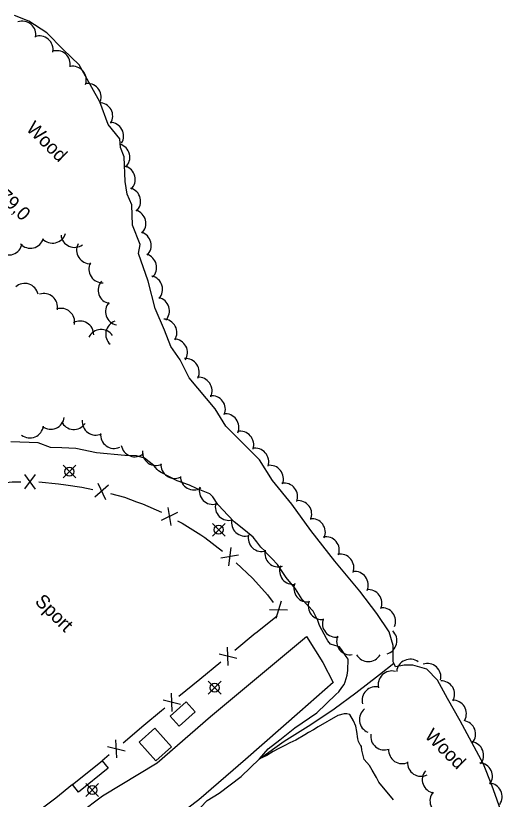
# Model space of a CAD drawing. Extents: x 642515 to 647219, y 6080136 to 6084356.
# Drawn here: x 643817.9 to 643926.8, y 6082164.2 to 6082337 of the extents above; entities that cross this region are included whole.
import ezdxf

# ---------------------------------------------------------------- set-up
doc = ezdxf.new("R2010")
doc.units = 0
for name, color, linetype in [('Level 1', 7, 'Continuous'), ('Level 19', 7, 'Continuous'), ('Level 3', 7, 'Continuous'), ('Level 31', 7, 'Continuous'), ('Level 36', 7, 'Continuous'), ('Level 37', 7, 'Continuous'), ('Level 4', 7, 'Continuous'), ('Level 44', 7, 'Continuous'), ('Level 56', 7, 'Continuous')]:
    doc.layers.add(name, color=color, linetype=linetype)

msp = doc.modelspace()

# ---------------------------------------------------------------- linework, layer by layer
at = {"layer": 'Level 1'}
for points in [[(643875.66, 6082215.94), (643874.38, 6082217.32), (643873.78, 6082217.85), (643873.18, 6082218.55), (643872.92, 6082218.93), (643871.95, 6082219.81), (643871.12, 6082220.93), (643870.3, 6082221.97), (643868.61, 6082223.42), (643866.09, 6082225.37), (643863.53, 6082228.06), (643862.76, 6082228.9), (643862.46, 6082229.17), (643861.41, 6082230.88), (643860.69, 6082231.53), (643857.76, 6082232.7), (643856.26, 6082233.43), (643853.5, 6082234.45), (643849.97, 6082236.24), (643849.38, 6082236.61), (643849.12, 6082236.92), (643848.39, 6082237.81), (643846.29, 6082239.39), (643844.52, 6082239.9), (643842.01, 6082240.01), (643835.7, 6082240.6), (643831.19, 6082241.57), (643828.07, 6082241.69), (643825.59, 6082241.76), (643822.83, 6082242.79), (643816.82, 6082243.03)], [(643894.75, 6082172.96), (643894.21, 6082174.98), (643894.17, 6082175.78), (643894.04, 6082176.05), (643893.91, 6082176.17), (643893.51, 6082176.91), (643893.36, 6082177.5), (643893.16, 6082179.14), (643892.94, 6082180.33), (643892.4, 6082181.51), (643891.56, 6082182.87), (643890.91, 6082183), (643890.34, 6082183.05), (643888.98, 6082182.66), (643884.61, 6082180.14), (643883.55, 6082179.48), (643882.49, 6082178.9), (643881.7, 6082178.38), (643879.7, 6082177.19), (643878.39, 6082176.6), (643877.28, 6082176.06), (643875.94, 6082175.34), (643874.72, 6082174.68), (643873.3, 6082173.8), (643871.64, 6082173.07), (643873.55, 6082175.29), (643876.13, 6082177.27), (643879.44, 6082179.9), (643884.34, 6082183.25), (643888.52, 6082187.25), (643889.16, 6082187.86), (643889.86, 6082188.8), (643890.33, 6082189.49), (643890.57, 6082190.05), (643891.02, 6082191.52), (643891.12, 6082192.55), (643891.2, 6082195.08), (643890.76, 6082195.7), (643890.33, 6082196.32), (643889.89, 6082197.02), (643889.28, 6082197.8), (643888.26, 6082198.1), (643887.31, 6082198.42), (643886.71, 6082199.11), (643886.48, 6082199.62), (643884.89, 6082202.51), (643884.51, 6082203.62), (643883.48, 6082205.69), (643881.05, 6082208.26), (643879.6, 6082210.56), (643877.58, 6082213.06), (643875.66, 6082215.94)], [(643901.25, 6082164.06), (643897.98, 6082167.98), (643897.45, 6082169), (643896.52, 6082170.6), (643895.91, 6082171.61), (643894.75, 6082172.96)]]:
    msp.add_lwpolyline(points, dxfattribs=at)
at = {"layer": 'Level 19'}
msp.add_lwpolyline([(643831.96, 6082161.14), (643837.04, 6082164.9), (643849.08, 6082172.18), (643860.87, 6082182.46), (643882.02, 6082200.06), (643885.62, 6082194.35), (643887.93, 6082189.96), (643880.56, 6082183.47), (643868.57, 6082172.98), (643858.29, 6082164.03), (643848.88, 6082156.93), (643843.91, 6082153.54), (643841.75, 6082152.29)], dxfattribs=at)
at = {"layer": 'Level 31'}
msp.add_lwpolyline([(643838.27, 6082171), (643831.76, 6082165.77), (643830.44, 6082167.41), (643836.99, 6082172.66), (643838.27, 6082171)], dxfattribs=at)
at = {"layer": 'Level 36'}
for p, q in [((643831.17, 6082235.05), (643828.35, 6082237.87)), ((643828.35, 6082235.05), (643831.17, 6082237.87)), ((643864.1, 6082222.22), (643861.28, 6082225.04)), ((643861.28, 6082222.22), (643864.1, 6082225.04)), ((643863.21, 6082187.38), (643860.39, 6082190.2)), ((643860.39, 6082187.38), (643863.21, 6082190.2)), ((643836.2, 6082164.8), (643833.38, 6082167.62)), ((643833.38, 6082164.8), (643836.2, 6082167.62))]:
    msp.add_line(p, q, dxfattribs=at)
for centre in [(643829.76, 6082236.46), (643862.69, 6082223.63), (643861.8, 6082188.79), (643834.79, 6082166.21)]:
    msp.add_circle(centre, 1, dxfattribs=at)
at = {"layer": 'Level 37'}
for p, q in [((643822.24, 6082235.81), (643819.83, 6082232.62)), ((643819.84, 6082235.82), (643822.23, 6082232.61)), ((643836.01, 6082233.93), (643837.74, 6082230.33)), ((643838.36, 6082233.47), (643835.39, 6082230.79)), ((643851.49, 6082228.53), (643852.14, 6082224.58)), ((643853.62, 6082227.42), (643850.02, 6082225.69)), ((643865.32, 6082219.68), (643864.87, 6082215.7)), ((643867.07, 6082218.03), (643863.12, 6082217.35)), ((643876.46, 6082207.85), (643875.31, 6082204.02)), ((643875.57, 6082204.53), (643870.85, 6082200.83)), ((643877.88, 6082205.92), (643873.89, 6082205.96)), ((643864.8, 6082193.72), (643864.6, 6082197.72)), ((643866.64, 6082195.26), (643862.75, 6082196.18)), ((643863.16, 6082194.44), (643858.52, 6082190.63)), ((643858.52, 6082190.63), (643853.89, 6082186.82)), ((643852.43, 6082183.56), (643852.25, 6082187.56)), ((643854.28, 6082185.08), (643850.4, 6082186.03)), ((643846.2, 6082180.42), (643841.61, 6082176.56)), ((643840.2, 6082173.28), (643839.97, 6082177.27)), ((643842.03, 6082174.82), (643838.14, 6082175.72)), ((643838.55, 6082173.98), (643836.99, 6082172.66)), ((643830.44, 6082167.41), (643826.77, 6082164.44))]:
    msp.add_line(p, q, dxfattribs=at)
for points in [[(643813.07, 6082233.79), (643817.14, 6082234.23), (643819.04, 6082234.22)], [(643823.04, 6082234.2), (643827.36, 6082233.75), (643829, 6082233.51)], [(643829, 6082233.51), (643832.48, 6082233), (643834.92, 6082232.52)], [(643838.82, 6082231.64), (643841.94, 6082230.81), (643844.52, 6082229.82)], [(643844.52, 6082229.82), (643845.84, 6082229.31), (643850.05, 6082227.47)], [(643853.6, 6082225.63), (643854.64, 6082225.09), (643858.71, 6082222.49)], [(643858.71, 6082222.49), (643859.64, 6082221.9), (643863.52, 6082218.91)], [(643866.55, 6082216.32), (643870.12, 6082212.95), (643870.85, 6082212.14)], [(643870.85, 6082212.14), (643873.45, 6082209.26), (643874.71, 6082207.55)], [(643870.85, 6082200.83), (643870.7, 6082200.72), (643866.23, 6082197)], [(643850.8, 6082184.28), (643850.04, 6082183.66), (643846.2, 6082180.42)], [(643826.77, 6082164.44), (643822.38, 6082161.1), (643821.9, 6082161.12)]]:
    msp.add_lwpolyline(points, dxfattribs=at)
at = {"layer": 'Level 4'}
for points in [[(643852.13, 6082264.04), (643850.71, 6082267.64), (643848.65, 6082272.42), (643847.1, 6082278.46), (643844.97, 6082284.55), (643845.36, 6082286.52), (643843.65, 6082290.84), (643843.49, 6082295.32), (643842.47, 6082297.63), (643842.07, 6082300.46), (643841.85, 6082305.92), (643841.01, 6082307.92), (643840.9, 6082309.87), (643838.28, 6082313), (643836.46, 6082318.04), (643831.9, 6082326.17), (643828.41, 6082329.54), (643824.78, 6082333.27), (643820.8, 6082335.84), (643817.68, 6082337.03)], [(643926.77, 6082156.3), (643922.91, 6082167.32), (643921.04, 6082171.95), (643915.96, 6082181.45), (643913.17, 6082186.43), (643910.91, 6082190.47), (643908.59, 6082192.87), (643905.52, 6082193.77), (643903.61, 6082193.79), (643901.63, 6082193.41), (643901.3, 6082194.2), (643901.17, 6082194.52), (643901.18, 6082198.07), (643900.28, 6082201.11), (643897.58, 6082205.17), (643893.81, 6082210.1), (643888.27, 6082216.7), (643883.02, 6082223.43), (643878.79, 6082229.24), (643874.52, 6082234.48), (643871.66, 6082239.05), (643868.99, 6082241.77), (643864.25, 6082246.49), (643861.92, 6082250.28), (643856.17, 6082257.16), (643854.16, 6082261.13), (643852.13, 6082264.04)], [(643845.87, 6082148.45), (643849.78, 6082152.72), (643854.12, 6082157.37), (643857.19, 6082160.78), (643860.15, 6082163.9), (643862.78, 6082165.54), (643867.62, 6082169.2), (643871.64, 6082173.07), (643877.12, 6082177.01), (643883.02, 6082180.65), (643888.12, 6082184.09), (643892.89, 6082187.67), (643898.13, 6082191.69), (643901.3, 6082194.2)]]:
    msp.add_lwpolyline(points, dxfattribs=at)
at = {"layer": 'Level 44'}
for centre, start, end in [((643819.35, 6082332.82), 349.4544, 109.4324), ((643823.15, 6082329.56), 349.4544, 109.4324), ((643826.95, 6082326.31), 349.4544, 109.4324), ((643830.48, 6082322.86), 340.9078, 100.8858), ((643833.76, 6082319.08), 340.9078, 100.8858), ((643836.31, 6082314.87), 328.7495, 88.7274), ((643838.71, 6082310.49), 328.7495, 88.7274), ((643840.08, 6082305.78), 313.9631, 73.941), ((643841.28, 6082300.93), 313.9631, 73.941), ((643842.46, 6082296.07), 313.5451, 73.523), ((643843.63, 6082291.21), 313.5451, 73.523), ((643826.03, 6082289.86), 223.1117, 343.0897), ((643844.8, 6082286.35), 313.781, 73.7589), ((643821.16, 6082288.73), 223.1117, 343.0897), ((643830.89, 6082288.92), 185.8795, 305.8574), ((643816.36, 6082287.24), 229.5062, 349.4841), ((643834.33, 6082285.31), 152.7566, 272.7345), ((643845.99, 6082281.49), 313.781, 73.7589), ((643837.04, 6082281.1), 152.7566, 272.7345), ((643847.31, 6082276.65), 317.5724, 77.5504), ((643819.91, 6082274.97), 11.8032, 131.7812), ((643839.08, 6082276.49), 138.9354, 258.9133), ((643824.15, 6082272.75), 348.8748, 108.8528), ((643840.7, 6082271.76), 138.9354, 258.9133), ((643848.82, 6082271.88), 317.5724, 77.5504), ((643827.91, 6082269.46), 348.8748, 108.8528), ((643850.46, 6082267.11), 327.915, 87.893), ((643832.11, 6082266.67), 358.6278, 118.6057), ((643840.75, 6082266.78), 108.4417, 228.4197), ((643836.74, 6082264.79), 33.4091, 153.387), ((643852.8, 6082262.7), 327.915, 87.893), ((643855.39, 6082258.39), 334.4749, 94.4528), ((643858.22, 6082254.27), 334.4749, 94.4528), ((643861.14, 6082250.19), 337.0956, 97.0736), ((643825.66, 6082248.8), 232.4915, 352.4694), ((643835.58, 6082247.5), 174.0407, 294.0186), ((643864.15, 6082246.2), 337.0956, 97.0736), ((643821.04, 6082246.89), 232.4915, 352.4694), ((643830.74, 6082248.75), 205.56, 325.5379), ((643839.62, 6082244.57), 174.0407, 294.0186), ((643867.4, 6082242.38), 341.4999, 101.4778), ((643844.16, 6082242.72), 189.7671, 309.745), ((643848.84, 6082240.8), 175.2473, 295.2252), ((643870.71, 6082238.63), 341.4999, 101.4778), ((643852.94, 6082237.95), 175.2473, 295.2252), ((643873.95, 6082234.84), 338.781, 98.759), ((643857.22, 6082235.42), 180.6933, 300.6712), ((643877.08, 6082230.94), 338.781, 98.759), ((643861.38, 6082232.22), 165.0588, 285.0367), ((643864.92, 6082228.69), 165.0588, 285.0367), ((643880.2, 6082227.05), 336.9941, 96.972), ((643868.5, 6082225.22), 167.3093, 287.2873), ((643883.21, 6082223.05), 336.9941, 96.972), ((643872.18, 6082221.83), 167.3093, 287.2873), ((643886.28, 6082219.09), 339.9417, 99.9197), ((643875.85, 6082218.43), 167.3093, 287.2873), ((643889.49, 6082215.25), 339.9417, 99.9197), ((643879.09, 6082214.58), 159.1847, 279.1627), ((643892.67, 6082211.42), 337.032, 97.01), ((643882.25, 6082210.7), 159.1847, 279.1627), ((643895.68, 6082207.42), 337.032, 97.01), ((643885.41, 6082206.82), 158.9023, 278.8802), ((643898.69, 6082203.43), 337.032, 97.01), ((643888.54, 6082202.93), 158.9023, 278.8802), ((643898.97, 6082199.15), 286.0401, 46.0181), ((643891.68, 6082199.04), 158.9023, 278.8802), ((643895.69, 6082197.56), 209.9271, 329.905), ((643904.91, 6082192.07), 54.0181, 173.9961), ((643908.68, 6082191.12), 348.1787, 108.1567), ((643900.85, 6082189.48), 74.6487, 194.6266), ((643897.29, 6082185.97), 74.6487, 194.6266), ((643911.71, 6082187.32), 331.2961, 91.2741), ((643914.3, 6082183.05), 331.2961, 91.2741), ((643896.7, 6082181.74), 128.0144, 247.9924), ((643916.33, 6082178.56), 320.8113, 80.7893), ((643899.21, 6082178.05), 170.2397, 290.2176), ((643918.1, 6082173.88), 320.8113, 80.7893), ((643903.15, 6082175.03), 176.0741, 296.052), ((643907.3, 6082172.23), 176.0741, 296.052), ((643920.03, 6082169.24), 325.5086, 85.4865), ((643910.56, 6082168.52), 139.933, 259.9109), ((643922.18, 6082164.73), 325.5086, 85.4865), ((643912.27, 6082163.82), 139.933, 259.9109)]:
    msp.add_arc(centre, 3, start, end, dxfattribs=at)
at = {"layer": 'Level 56'}
for points in [[(643855.52, 6082185.68), (643857.48, 6082183.46), (643853.95, 6082180.33), (643851.98, 6082182.54), (643855.52, 6082185.68)], [(643848.83, 6082172.66), (643852.29, 6082175.74), (643848.61, 6082179.88), (643845.15, 6082176.8), (643848.83, 6082172.66)]]:
    msp.add_lwpolyline(points, dxfattribs=at)

# ---------------------------------------------------------------- texts
at = {"layer": 'Level 3'}
msp.add_text('479,0', height=3, rotation=315.59, dxfattribs=at).set_placement((643812.21, 6082298.58))
at = {"layer": 'Level 44'}
for p in [(643820.04, 6082311.91), (643907.91, 6082177.97)]:
    msp.add_text('Wood', height=3, rotation=315.1749, dxfattribs=at).set_placement(p)
at = {"layer": 'Level 56'}
msp.add_text('Sport', height=3, rotation=315.1749, dxfattribs=at).set_placement((643821.96, 6082207.62))

doc.saveas('drawing.dxf')
